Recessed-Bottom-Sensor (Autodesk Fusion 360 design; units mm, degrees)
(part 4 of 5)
work_plane "WorkPlane63" AlongDistance 20.8 ExtraOffset 0
sketch "Clear stocked carriage screw tip beyond insert" plane through (0, 20.8, 0) normal (0, 1, 0) x axis (1, 0, 0)
  circle C1 centre (60.15, -65) radius 1.7
extrude "Extrude63" cut sketch "Clear stocked carriage screw tip beyond insert" along normal blind 0.6
work_plane "WorkPlane64" AlongDistance -21.4 ExtraOffset 0
sketch "Clear stocked carriage screw tip beyond insert (1)" plane through (0, -21.4, 0) normal (0, 1, 0) x axis (1, 0, 0)
  circle C1 centre (60.15, -65) radius 1.7
extrude "Extrude64" cut sketch "Clear stocked carriage screw tip beyond insert (1)" along normal blind 0.6
work_plane "WorkPlane22" AlongDistance -2.5 ExtraOffset 0
sketch "Support-free lower ramp under left inner-race pad" plane through (0, -2.5, 0) normal (0, 1, 0) x axis (1, 0, 0)
  line L1 (8.1, -9.5) -> (7, -9.5)
  line L2 (8.1, -10.7) -> (8.1, -9.5)
  line L3 (7, -9.6) -> (8.1, -10.7)
  line L4 (7, -9.5) -> (7, -9.6)
extrude "Extrude22" cut sketch "Support-free lower ramp under left inner-race pad" along normal blind 5
work_plane "WorkPlane23" AlongDistance -2.5 ExtraOffset 0
sketch "Support-free lower ramp under right inner-race pad" plane through (0, -2.5, 0) normal (0, 1, 0) x axis (1, 0, 0)
  line L1 (17, -9.5) -> (15.9, -9.5)
  line L2 (17, -9.6) -> (17, -9.5)
  line L3 (15.9, -10.7) -> (17, -9.6)
  line L4 (15.9, -9.5) -> (15.9, -10.7)
extrude "Extrude23" cut sketch "Support-free lower ramp under right inner-race pad" along normal blind 5
ground "Pin94"
ground "Pin95"
ground "Pin100"
ground "Pin101"
ground "Pin102"
ground "Pin103"
ground "Pin104"
ground "Pin105"
ground "Pin106"
ground "Pin107"
ground "Pin108"
ground "Pin109"
ground "Pin110"
ground "Pin111"
ground "Pin112"
ground "Pin113"
ground "Pin120"
ground "Pin121"
ground "Pin122"
ground "Pin123"
work_plane "WorkPlane65" AlongDistance 36 ExtraOffset 0
sketch "Remove Oldham carriage extensions" plane through (36, 0, 0) normal (1, 0, 0) x axis (0, 0, -1)
  line L1 (-46, 34) -> (-46, -34)
  line L2 (-84, 34) -> (-46, 34)
  line L3 (-84, -34) -> (-84, 34)
  line L4 (-46, -34) -> (-84, -34)
extrude "Extrude65" cut sketch "Remove Oldham carriage extensions" along normal blind 30.3
work_plane "WorkPlane66" AlongDistance 24 ExtraOffset 0
sketch "Upper geared sensor support" plane through (24, 0, 0) normal (1, 0, 0) x axis (0, 0, -1)
  line L1 (-78, -10) -> (-78, -23)
  line L2 (-126, -10) -> (-78, -10)
  line L3 (-126, -23) -> (-126, -10)
  line L4 (-78, -23) -> (-126, -23)
extrude "Extrude66" add sketch "Upper geared sensor support" along normal blind 10
work_plane "WorkPlane67" AlongDistance 24 ExtraOffset 0
sketch "Geared mount M3 insert from inboard face" plane through (24, 0, 0) normal (1, 0, 0) x axis (0, 0, -1)
  circle C1 centre (-110.15, -16) radius 2
extrude "Extrude67" cut sketch "Geared mount M3 insert from inboard face" along normal blind 6.8
work_plane "WorkPlane68" AlongDistance 30.7 ExtraOffset 0
sketch "Geared mount screw clearance" plane through (30.7, 0, 0) normal (1, 0, 0) x axis (0, 0, -1)
  circle C1 centre (-110.15, -16) radius 1.7
extrude "Extrude68" cut sketch "Geared mount screw clearance" along normal blind 3.4
work_plane "WorkPlane69" AlongDistance 24 ExtraOffset 0
sketch "Upper geared sensor support (1)" plane through (24, 0, 0) normal (1, 0, 0) x axis (0, 0, -1)
  line L1 (-78, 23) -> (-78, 10)
  line L2 (-126, 23) -> (-78, 23)
  line L3 (-126, 10) -> (-126, 23)
  line L4 (-78, 10) -> (-126, 10)
extrude "Extrude69" add sketch "Upper geared sensor support (1)" along normal blind 10
work_plane "WorkPlane70" AlongDistance 24 ExtraOffset 0
sketch "Geared mount M3 insert from inboard face (1)" plane through (24, 0, 0) normal (1, 0, 0) x axis (0, 0, -1)
  circle C1 centre (-110.15, 16) radius 2
extrude "Extrude70" cut sketch "Geared mount M3 insert from inboard face (1)" along normal blind 6.8
work_plane "WorkPlane71" AlongDistance 30.7 ExtraOffset 0
sketch "Geared mount screw clearance (1)" plane through (30.7, 0, 0) normal (1, 0, 0) x axis (0, 0, -1)
  circle C1 centre (-110.15, 16) radius 1.7
extrude "Extrude71" cut sketch "Geared mount screw clearance (1)" along normal blind 3.4
work_plane "WorkPlane1" AlongDistance -37.35 ExtraOffset 0
sketch "Continuous 12 mm journals" plane through (-37.35, 0, 0) normal (1, 0, 0) x axis (0, 0, -1)
  circle C1 centre (-65, 0) radius 6
extrude "Extrude1" new body sketch "Continuous 12 mm journals" along normal blind 74.7 bodies "P05G Shaft lower half"
work_plane "WorkPlane2" AlongDistance -23.8 ExtraOffset 0
sketch "Structural shaft" plane through (-23.8, 0, 0) normal (1, 0, 0) x axis (0, 0, -1)
  circle C1 centre (-65, 0) radius 8
extrude "Extrude2" add sketch "Structural shaft" along normal blind 47.6
work_plane "WorkPlane3" AlongDistance -23.9 ExtraOffset 0
sketch "Rotor D flat" plane through (-23.9, 0, 0) normal (1, 0, 0) x axis (0, 0, -1)
  line L1 (-56, 9) -> (-56, 6.5)
  line L2 (-74, 9) -> (-56, 9)
  line L3 (-74, 6.5) -> (-74, 9)
  line L4 (-56, 6.5) -> (-74, 6.5)
extrude "Extrude3" cut sketch "Rotor D flat" along normal blind 47.8
work_plane "WorkPlane4" AlongDistance 37.35 ExtraOffset 0
sketch "Retain axial shoulder" plane through (37.35, 0, 0) normal (1, 0, 0) x axis (0, 0, -1)
  circle C1 centre (-65, 0) radius 10
extrude "Extrude4" add sketch "Retain axial shoulder" along normal blind 3
work_plane "WorkPlane5" AlongDistance 40.35 ExtraOffset 0
sketch "Short D drive stub" plane through (40.35, 0, 0) normal (1, 0, 0) x axis (0, 0, -1)
  circle C1 centre (-65, 0) radius 4
extrude "Extrude5" add sketch "Short D drive stub" along normal blind 8
work_plane "WorkPlane6" AlongDistance 40.35 ExtraOffset 0
sketch "Drive stub D flat" plane through (40.35, 0, 0) normal (1, 0, 0) x axis (0, 0, -1)
  line L1 (-60, 5) -> (-60, 3.2)
  line L2 (-70, 5) -> (-60, 5)
  line L3 (-70, 3.2) -> (-70, 5)
  line L4 (-60, 3.2) -> (-70, 3.2)
extrude "Extrude6" cut sketch "Drive stub D flat" along normal blind 8.15
work_plane "WorkPlane7" AlongDistance -37.45 ExtraOffset 0
sketch "End retention insert" plane through (-37.45, 0, 0) normal (1, 0, 0) x axis (0, 0, -1)
  circle C1 centre (-65, 0) radius 2
extrude "Extrude7" cut sketch "End retention insert" along normal blind 6.8
work_plane "WorkPlane8" AlongDistance -6.8 ExtraOffset 0
sketch "Joining insert" plane through (0, -6.8, 0) normal (0, 1, 0) x axis (1, 0, 0)
  circle C1 centre (-15, -65) radius 2
extrude "Extrude8" cut sketch "Joining insert" along normal blind 6.9
work_plane "WorkPlane9" AlongDistance -0.1 ExtraOffset 0
sketch "Joining screw clearance" plane through (0, -0.1, 0) normal (0, 1, 0) x axis (1, 0, 0)
  circle C1 centre (-15, -65) radius 1.7
extrude "Extrude9" cut sketch "Joining screw clearance" along normal blind 6.7
work_plane "WorkPlane10" AlongDistance 3.5 ExtraOffset 0
sketch "Recessed cap head" plane through (0, 3.5, 0) normal (0, 1, 0) x axis (1, 0, 0)
  circle C1 centre (-15, -65) radius 3.1
extrude "Extrude10" cut sketch "Recessed cap head" along normal blind 3.1
work_plane "WorkPlane11" AlongDistance -6.8 ExtraOffset 0
sketch "Joining insert (1)" plane through (0, -6.8, 0) normal (0, 1, 0) x axis (1, 0, 0)
  circle C1 centre (15, -65) radius 2
extrude "Extrude11" cut sketch "Joining insert (1)" along normal blind 6.9
work_plane "WorkPlane12" AlongDistance -0.1 ExtraOffset 0
sketch "Joining screw clearance (1)" plane through (0, -0.1, 0) normal (0, 1, 0) x axis (1, 0, 0)
  circle C1 centre (15, -65) radius 1.7
extrude "Extrude12" cut sketch "Joining screw clearance (1)" along normal blind 6.7
work_plane "WorkPlane13" AlongDistance 3.5 ExtraOffset 0
sketch "Recessed cap head (1)" plane through (0, 3.5, 0) normal (0, 1, 0) x axis (1, 0, 0)
  circle C1 centre (15, -65) radius 3.1
extrude "Extrude13" cut sketch "Recessed cap head (1)" along normal blind 3.1
work_plane "WorkPlane14" AlongDistance -6.6 ExtraOffset 0
sketch "Retain alignment key pocket" plane through (-6.6, 0, 0) normal (1, 0, 0) x axis (0, 0, -1)
  line L1 (-61, 1.6) -> (-61, -1.6)
  line L2 (-69, 1.6) -> (-61, 1.6)
  line L3 (-69, -1.6) -> (-69, 1.6)
  line L4 (-61, -1.6) -> (-69, -1.6)
extrude "Extrude14" cut sketch "Retain alignment key pocket" along normal blind 3.2
work_plane "WorkPlane15" AlongDistance 3.4 ExtraOffset 0
sketch "Retain alignment key pocket (1)" plane through (3.4, 0, 0) normal (1, 0, 0) x axis (0, 0, -1)
  line L1 (-61, 1.6) -> (-61, -1.6)
  line L2 (-69, 1.6) -> (-61, 1.6)
  line L3 (-69, -1.6) -> (-69, 1.6)
  line L4 (-61, -1.6) -> (-69, -1.6)
extrude "Extrude15" cut sketch "Retain alignment key pocket (1)" along normal blind 3.2
split "Split1" bodies "P05G Shaft upper half"
work_plane "WorkPlane1" AlongDistance 40.5 ExtraOffset 0
sketch "Involute gear polygon m1.25 pressure20" plane through (40.5, 0, 0) normal (1, 0, 0) x axis (0, 0, -1)
  line L1 (-63.7058, 28.408) -> (-63.7058, 28.408)
  line L2 (-63.7507, 28.7619) -> (-63.7058, 28.408)
  line L3 (-63.8186, 29.1167) -> (-63.7507, 28.7619)
  line L4 (-63.9051, 29.4719) -> (-63.8186, 29.1167)
  line L5 (-64.0079, 29.8273) -> (-63.9051, 29.4719)
  line L6 (-64.1255, 30.1826) -> (-64.0079, 29.8273)
  line L7 (-64.257, 30.5378) -> (-64.1255, 30.1826)
  line L8 (-64.4015, 30.8926) -> (-64.257, 30.5378)
  line L9 (-64.5586, 31.2469) -> (-64.4015, 30.8926)
  line L10 (-65.4414, 31.2469) -> (-64.5586, 31.2469)
  line L11 (-65.5985, 30.8926) -> (-65.4414, 31.2469)
  line L12 (-65.743, 30.5378) -> (-65.5985, 30.8926)
  line L13 (-65.8745, 30.1826) -> (-65.743, 30.5378)
  line L14 (-65.9921, 29.8273) -> (-65.8745, 30.1826)
  line L15 (-66.0949, 29.4719) -> (-65.9921, 29.8273)
  line L16 (-66.1814, 29.1167) -> (-66.0949, 29.4719)
  line L17 (-66.2493, 28.7619) -> (-66.1814, 29.1167)
  line L18 (-66.2942, 28.408) -> (-66.2493, 28.7619)
  line L19 (-66.2942, 28.408) -> (-66.2942, 28.408)
  line L20 (-66.5771, 28.3937) -> (-66.2942, 28.408)
  line L21 (-66.8599, 28.3766) -> (-66.5771, 28.3937)
  line L22 (-67.1425, 28.3567) -> (-66.8599, 28.3766)
  line L23 (-67.4248, 28.3339) -> (-67.1425, 28.3567)
  line L24 (-67.4248, 28.3339) -> (-67.4248, 28.3339)
  line L25 (-67.5156, 28.6789) -> (-67.4248, 28.3339)
  line L26 (-67.6292, 29.0218) -> (-67.5156, 28.6789)
  line L27 (-67.7613, 29.3626) -> (-67.6292, 29.0218)
  line L28 (-67.9096, 29.7016) -> (-67.7613, 29.3626)
  line L29 (-68.0726, 30.0386) -> (-67.9096, 29.7016)
  line L30 (-68.2493, 30.3736) -> (-68.0726, 30.0386)
  line L31 (-68.4389, 30.7065) -> (-68.2493, 30.3736)
  line L32 (-68.6409, 31.0372) -> (-68.4389, 30.7065)
  line L33 (-69.5162, 30.9219) -> (-68.6409, 31.0372)
  line L34 (-69.6257, 30.5502) -> (-69.5162, 30.9219)
  line L35 (-69.7227, 30.1796) -> (-69.6257, 30.5502)
  line L36 (-69.8066, 29.8103) -> (-69.7227, 30.1796)
  line L37 (-69.8769, 29.4426) -> (-69.8066, 29.8103)
  line L38 (-69.9324, 29.0768) -> (-69.8769, 29.4426)
  line L39 (-69.9718, 28.7134) -> (-69.9324, 29.0768)
  line L40 (-69.9928, 28.3528) -> (-69.9718, 28.7134)
  line L41 (-69.9911, 27.9961) -> (-69.9928, 28.3528)
  line L42 (-69.9911, 27.9961) -> (-69.9911, 27.9961)
  line L43 (-70.2698, 27.945) -> (-69.9911, 27.9961)
  line L44 (-70.5479, 27.8911) -> (-70.2698, 27.945)
  line L45 (-70.8254, 27.8344) -> (-70.5479, 27.8911)
  line L46 (-71.1024, 27.775) -> (-70.8254, 27.8344)
  line L47 (-71.1024, 27.775) -> (-71.1024, 27.775)
  line L48 (-71.2374, 28.1052) -> (-71.1024, 27.775)
  line L49 (-71.3948, 28.4303) -> (-71.2374, 28.1052)
  line L50 (-71.5703, 28.751) -> (-71.3948, 28.4303)
  line L51 (-71.7616, 29.0677) -> (-71.5703, 28.751)
  line L52 (-71.9672, 29.3805) -> (-71.7616, 29.0677)
  line L53 (-72.1861, 29.6896) -> (-71.9672, 29.3805)
  line L54 (-72.4175, 29.9949) -> (-72.1861, 29.6896)
  line L55 (-72.6609, 30.2964) -> (-72.4175, 29.9949)
  line L56 (-73.5136, 30.0679) -> (-72.6609, 30.2964)
  line L57 (-73.5737, 29.6851) -> (-73.5136, 30.0679)
  line L58 (-73.6215, 29.305) -> (-73.5737, 29.6851)
  line L59 (-73.6565, 28.9279) -> (-73.6215, 29.305)
  line L60 (-73.6782, 28.5541) -> (-73.6565, 28.9279)
  line L61 (-73.6854, 28.1843) -> (-73.6782, 28.5541)
  line L62 (-73.6771, 27.8188) -> (-73.6854, 28.1843)
  line L63 (-73.6509, 27.4586) -> (-73.6771, 27.8188)
  line L64 (-73.6027, 27.1051) -> (-73.6509, 27.4586)
  line L65 (-73.6027, 27.1051) -> (-73.6027, 27.1051)
  line L66 (-73.8722, 27.018) -> (-73.6027, 27.1051)
  line L67 (-74.1409, 26.9283) -> (-73.8722, 27.018)
  line L68 (-74.4087, 26.8359) -> (-74.1409, 26.9283)
  line L69 (-74.6756, 26.7409) -> (-74.4087, 26.8359)
  line L70 (-74.6756, 26.7409) -> (-74.6756, 26.7409)
  line L71 (-74.8525, 27.0507) -> (-74.6756, 26.7409)
  line L72 (-75.051, 27.3524) -> (-74.8525, 27.0507)
  line L73 (-75.2669, 27.6474) -> (-75.051, 27.3524)
  line L74 (-75.4978, 27.9365) -> (-75.2669, 27.6474)
  line L75 (-75.7425, 28.2198) -> (-75.4978, 27.9365)
  line L76 (-75.9999, 28.4976) -> (-75.7425, 28.2198)
  line L77 (-76.2692, 28.7701) -> (-75.9999, 28.4976)
  line L78 (-76.5499, 29.0373) -> (-76.2692, 28.7701)
  line L79 (-77.3655, 28.6994) -> (-76.5499, 29.0373)
  line L80 (-77.375, 28.3121) -> (-77.3655, 28.6994)
  line L81 (-77.3728, 27.9289) -> (-77.375, 28.3121)
  line L82 (-77.3583, 27.5505) -> (-77.3728, 27.9289)
  line L83 (-77.331, 27.1771) -> (-77.3583, 27.5505)
  line L84 (-77.2899, 26.8095) -> (-77.331, 27.1771)
  line L85 (-77.2339, 26.4482) -> (-77.2899, 26.8095)
  line L86 (-77.1609, 26.0945) -> (-77.2339, 26.4482)
  line L87 (-77.067, 25.7503) -> (-77.1609, 26.0945)
  line L88 (-77.067, 25.7503) -> (-77.067, 25.7503)
  line L89 (-77.3229, 25.6288) -> (-77.067, 25.7503)
  line L90 (-77.5776, 25.5048) -> (-77.3229, 25.6288)
  line L91 (-77.831, 25.3783) -> (-77.5776, 25.5048)
  line L92 (-78.0832, 25.2492) -> (-77.831, 25.3783)
  line L93 (-78.0832, 25.2492) -> (-78.0832, 25.2492)
  line L94 (-78.299, 25.5332) -> (-78.0832, 25.2492)
  line L95 (-78.5352, 25.8065) -> (-78.299, 25.5332)
  line L96 (-78.7877, 26.0708) -> (-78.5352, 25.8065)
  line L97 (-79.0544, 26.3272) -> (-78.7877, 26.0708)
  line L98 (-79.334, 26.5762) -> (-79.0544, 26.3272)
  line L99 (-79.6254, 26.8181) -> (-79.334, 26.5762)
  line L100 (-79.928, 27.0531) -> (-79.6254, 26.8181)
  line L101 (-80.2412, 27.2813) -> (-79.928, 27.0531)
  line L102 (-81.0057, 26.8399) -> (-80.2412, 27.2813)
  line L103 (-80.9646, 26.4546) -> (-81.0057, 26.8399)
  line L104 (-80.9124, 26.075) -> (-80.9646, 26.4546)
  line L105 (-80.8487, 25.7017) -> (-80.9124, 26.075)
  line L106 (-80.7728, 25.3351) -> (-80.8487, 25.7017)
  line L107 (-80.6841, 24.9759) -> (-80.7728, 25.3351)
  line L108 (-80.5814, 24.6251) -> (-80.6841, 24.9759)
  line L109 (-80.4629, 24.2839) -> (-80.5814, 24.6251)
  line L110 (-80.3249, 23.955) -> (-80.4629, 24.2839)
  line L111 (-80.3249, 23.955) -> (-80.3249, 23.955)
  line L112 (-80.5627, 23.8011) -> (-80.3249, 23.955)
  line L113 (-80.799, 23.6449) -> (-80.5627, 23.8011)
  line L114 (-81.0338, 23.4864) -> (-80.799, 23.6449)
  line L115 (-81.2669, 23.3255) -> (-81.0338, 23.4864)
  line L116 (-81.2669, 23.3255) -> (-81.2669, 23.3255)
  line L117 (-81.518, 23.5789) -> (-81.2669, 23.3255)
  line L118 (-81.7879, 23.819) -> (-81.518, 23.5789)
  line L119 (-82.0727, 24.0481) -> (-81.7879, 23.819)
  line L120 (-82.3706, 24.2675) -> (-82.0727, 24.0481)
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extrude "Extrude1" new body sketch "Involute gear polygon m1.25 pressure20" along normal blind 8 bodies "G01R 48T gear with upper clamp"
work_plane "WorkPlane2" AlongDistance 40.4 ExtraOffset 0
sketch "Shaft bore" plane through (40.4, 0, 0) normal (1, 0, 0) x axis (0, 0, -1)
  circle C1 centre (-65, 0) radius 4.1
extrude "Extrude2" cut sketch "Shaft bore" along normal blind 8.2
work_plane "WorkPlane3" AlongDistance 40.5 ExtraOffset 0
sketch "D key flat" plane through (40.5, 0, 0) normal (1, 0, 0) x axis (0, 0, -1)
  line L1 (-62, 4.3) -> (-62, 3.35)
  line L2 (-68, 4.3) -> (-62, 4.3)
  line L3 (-68, 3.35) -> (-68, 4.3)
  line L4 (-62, 3.35) -> (-68, 3.35)
extrude "Extrude3" add sketch "D key flat" along normal blind 8
work_plane "WorkPlane4" AlongDistance 40.4 ExtraOffset 0
sketch "Clamp slit outside operating mesh sector" plane through (40.4, 0, 0) normal (1, 0, 0) x axis (0, 0, -1)
  line L1 (-32, 0.2) -> (-32, -0.2)
  line L2 (-65, 0.2) -> (-32, 0.2)
  line L3 (-65, -0.2) -> (-65, 0.2)
  line L4 (-32, -0.2) -> (-65, -0.2)
work_plane "WorkPlane5" AlongDistance -8 ExtraOffset 0
sketch "Clamp heat-set insert pocket" plane through (0, -8, 0) normal (0, 1, 0) x axis (1, 0, 0)
  circle C1 centre (44.5, -57) radius 2
work_plane "WorkPlane6" AlongDistance -1.3 ExtraOffset 0
sketch "Clamp through screw" plane through (0, -1.3, 0) normal (0, 1, 0) x axis (1, 0, 0)
  circle C1 centre (44.5, -57) radius 1.7
work_plane "WorkPlane7" AlongDistance 5 ExtraOffset 0
sketch "Recessed clamp screw head and tool path" plane through (0, 5, 0) normal (0, 1, 0) x axis (1, 0, 0)
  circle C1 centre (44.5, -57) radius 3.1
work_plane "WorkPlane1" AlongDistance 40.5 ExtraOffset 0
sketch "Involute gear polygon m1.25 pressure20" plane through (40.5, 0, 0) normal (1, 0, 0) x axis (0, 0, -1)
  line L1 (-110.8997, 14.0754) -> (-110.8647, 13.4185)
  line L2 (-110.9494, 14.3425) -> (-110.8997, 14.0754)
  line L3 (-111.0295, 14.6076) -> (-110.9494, 14.3425)
  line L4 (-111.1304, 14.8711) -> (-111.0295, 14.6076)
  line L5 (-111.2488, 15.1329) -> (-111.1304, 14.8711)
  line L6 (-111.383, 15.3927) -> (-111.2488, 15.1329)
  line L7 (-111.5317, 15.6505) -> (-111.383, 15.3927)
  line L8 (-111.6943, 15.9059) -> (-111.5317, 15.6505)
  line L9 (-111.87, 16.1587) -> (-111.6943, 15.9059)
  line L10 (-112.6708, 16.0533) -> (-111.87, 16.1587)
  line L11 (-112.7751, 15.7636) -> (-112.6708, 16.0533)
  line L12 (-112.866, 15.4748) -> (-112.7751, 15.7636)
  line L13 (-112.943, 15.1873) -> (-112.866, 15.4748)
  line L14 (-113.0053, 14.9016) -> (-112.943, 15.1873)
  line L15 (-113.0519, 14.6181) -> (-113.0053, 14.9016)
  line L16 (-113.0812, 14.3375) -> (-113.0519, 14.6181)
  line L17 (-113.0899, 14.0607) -> (-113.0812, 14.3375)
  line L18 (-113.0688, 13.7899) -> (-113.0899, 14.0607)
  line L19 (-112.9326, 13.1462) -> (-113.0688, 13.7899)
  line L20 (-113.2814, 13.0676) -> (-112.9326, 13.1462)
  line L21 (-113.6279, 12.9796) -> (-113.2814, 13.0676)
  line L22 (-113.9719, 12.8825) -> (-113.6279, 12.9796)
  line L23 (-114.3133, 12.7763) -> (-113.9719, 12.8825)
  line L24 (-114.5171, 13.4018) -> (-114.3133, 12.7763)
  line L25 (-114.6343, 13.6468) -> (-114.5171, 13.4018)
  line L26 (-114.7803, 13.8822) -> (-114.6343, 13.6468)
  line L27 (-114.9459, 14.1106) -> (-114.7803, 13.8822)
  line L28 (-115.128, 14.3328) -> (-114.9459, 14.1106)
  line L29 (-115.3249, 14.5491) -> (-115.128, 14.3328)
  line L30 (-115.5353, 14.7596) -> (-115.3249, 14.5491)
  line L31 (-115.7584, 14.9642) -> (-115.5353, 14.7596)
  line L32 (-115.9936, 15.1629) -> (-115.7584, 14.9642)
  line L33 (-116.7398, 14.8539) -> (-115.9936, 15.1629)
  line L34 (-116.7656, 14.547) -> (-116.7398, 14.8539)
  line L35 (-116.7786, 14.2446) -> (-116.7656, 14.547)
  line L36 (-116.7786, 13.947) -> (-116.7786, 14.2446)
  line L37 (-116.7649, 13.6548) -> (-116.7786, 13.947)
  line L38 (-116.7365, 13.3689) -> (-116.7649, 13.6548)
  line L39 (-116.6921, 13.0903) -> (-116.7365, 13.3689)
  line L40 (-116.6289, 12.8206) -> (-116.6921, 13.0903)
  line L41 (-116.5385, 12.5645) -> (-116.6289, 12.8206)
  line L42 (-116.2403, 11.9781) -> (-116.5385, 12.5645)
  line L43 (-116.5568, 11.8118) -> (-116.2403, 11.9781)
  line L44 (-116.8688, 11.6372) -> (-116.5568, 11.8118)
  line L45 (-117.176, 11.4544) -> (-116.8688, 11.6372)
  line L46 (-117.4782, 11.2634) -> (-117.176, 11.4544)
  line L47 (-117.837, 11.8148) -> (-117.4782, 11.2634)
  line L48 (-118.0136, 12.0212) -> (-117.837, 11.8148)
  line L49 (-118.2155, 12.2108) -> (-118.0136, 12.0212)
  line L50 (-118.4346, 12.3885) -> (-118.2155, 12.2108)
  line L51 (-118.668, 12.556) -> (-118.4346, 12.3885)
  line L52 (-118.9141, 12.714) -> (-118.668, 12.556)
  line L53 (-119.1718, 12.8628) -> (-118.9141, 12.714)
  line L54 (-119.4403, 13.0028) -> (-119.1718, 12.8628)
  line L55 (-119.7189, 13.1339) -> (-119.4403, 13.0028)
  line L56 (-120.3597, 12.6422) -> (-119.7189, 13.1339)
  line L57 (-120.3052, 12.3391) -> (-120.3597, 12.6422)
  line L58 (-120.2395, 12.0436) -> (-120.3052, 12.3391)
  line L59 (-120.1625, 11.7561) -> (-120.2395, 12.0436)
  line L60 (-120.0736, 11.4775) -> (-120.1625, 11.7561)
  line L61 (-119.9722, 11.2087) -> (-120.0736, 11.4775)
  line L62 (-119.8572, 10.951) -> (-119.9722, 11.2087)
  line L63 (-119.7264, 10.7069) -> (-119.8572, 10.951)
  line L64 (-119.5727, 10.4829) -> (-119.7264, 10.7069)
  line L65 (-119.1329, 9.9937) -> (-119.5727, 10.4829)
  line L66 (-119.3956, 9.7512) -> (-119.1329, 9.9937)
  line L67 (-119.6517, 9.5017) -> (-119.3956, 9.7512)
  line L68 (-119.9012, 9.2456) -> (-119.6517, 9.5017)
  line L69 (-120.1437, 8.9829) -> (-119.9012, 9.2456)
  line L70 (-120.6329, 9.4227) -> (-120.1437, 8.9829)
  line L71 (-120.8569, 9.5764) -> (-120.6329, 9.4227)
  line L72 (-121.101, 9.7072) -> (-120.8569, 9.5764)
  line L73 (-121.3587, 9.8222) -> (-121.101, 9.7072)
  line L74 (-121.6275, 9.9236) -> (-121.3587, 9.8222)
  line L75 (-121.9061, 10.0125) -> (-121.6275, 9.9236)
  line L76 (-122.1936, 10.0895) -> (-121.9061, 10.0125)
  line L77 (-122.4891, 10.1552) -> (-122.1936, 10.0895)
  line L78 (-122.7922, 10.2097) -> (-122.4891, 10.1552)
  line L79 (-123.2839, 9.5689) -> (-122.7922, 10.2097)
  line L80 (-123.1528, 9.2903) -> (-123.2839, 9.5689)
  line L81 (-123.0128, 9.0218) -> (-123.1528, 9.2903)
  line L82 (-122.864, 8.7641) -> (-123.0128, 9.0218)
  line L83 (-122.706, 8.518) -> (-122.864, 8.7641)
  line L84 (-122.5385, 8.2846) -> (-122.706, 8.518)
  line L85 (-122.3608, 8.0655) -> (-122.5385, 8.2846)
  line L86 (-122.1712, 7.8636) -> (-122.3608, 8.0655)
  line L87 (-121.9648, 7.687) -> (-122.1712, 7.8636)
  line L88 (-121.4134, 7.3282) -> (-121.9648, 7.687)
  line L89 (-121.6044, 7.026) -> (-121.4134, 7.3282)
  line L90 (-121.7872, 6.7187) -> (-121.6044, 7.026)
  line L91 (-121.9618, 6.4068) -> (-121.7872, 6.7187)
  line L92 (-122.1281, 6.0903) -> (-121.9618, 6.4068)
  line L93 (-122.7145, 6.3885) -> (-122.1281, 6.0903)
  line L94 (-122.9706, 6.4789) -> (-122.7145, 6.3885)
  line L95 (-123.2403, 6.5421) -> (-122.9706, 6.4789)
  line L96 (-123.5189, 6.5865) -> (-123.2403, 6.5421)
  line L97 (-123.8048, 6.6149) -> (-123.5189, 6.5865)
  line L98 (-124.097, 6.6286) -> (-123.8048, 6.6149)
  line L99 (-124.3946, 6.6286) -> (-124.097, 6.6286)
  line L100 (-124.697, 6.6156) -> (-124.3946, 6.6286)
  line L101 (-125.0039, 6.5898) -> (-124.697, 6.6156)
  line L102 (-125.3129, 5.8436) -> (-125.0039, 6.5898)
  line L103 (-125.1142, 5.6084) -> (-125.3129, 5.8436)
  line L104 (-124.9096, 5.3853) -> (-125.1142, 5.6084)
  line L105 (-124.6991, 5.1749) -> (-124.9096, 5.3853)
  line L106 (-124.4828, 4.978) -> (-124.6991, 5.1749)
  line L107 (-124.2606, 4.7959) -> (-124.4828, 4.978)
  line L108 (-124.0322, 4.6303) -> (-124.2606, 4.7959)
  line L109 (-123.7968, 4.4843) -> (-124.0322, 4.6303)
  line L110 (-123.5518, 4.3671) -> (-123.7968, 4.4843)
  line L111 (-122.9263, 4.1633) -> (-123.5518, 4.3671)
  line L112 (-123.0325, 3.8219) -> (-122.9263, 4.1633)
  line L113 (-123.1296, 3.4779) -> (-123.0325, 3.8219)
  line L114 (-123.2176, 3.1314) -> (-123.1296, 3.4779)
  line L115 (-123.2962, 2.7826) -> (-123.2176, 3.1314)
  line L116 (-123.9399, 2.9188) -> (-123.2962, 2.7826)
  line L117 (-124.2107, 2.9399) -> (-123.9399, 2.9188)
  line L118 (-124.4875, 2.9312) -> (-124.2107, 2.9399)
  line L119 (-124.7681, 2.9019) -> (-124.4875, 2.9312)
  line L120 (-125.0516, 2.8553) -> (-124.7681, 2.9019)
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extrude "Extrude1" new body sketch "Involute gear polygon m1.25 pressure20" along normal blind 8 bodies "G02 24T sensor pinion"
work_plane "WorkPlane2" AlongDistance 40.4 ExtraOffset 0
sketch "Shaft bore" plane through (40.4, 0, 0) normal (1, 0, 0) x axis (0, 0, -1)
  circle C1 centre (-110.15, 0) radius 3.1
extrude "Extrude2" cut sketch "Shaft bore" along normal blind 8.2
work_plane "WorkPlane3" AlongDistance 40.4 ExtraOffset 0
sketch "Sensor bushing end relief" plane through (40.4, 0, 0) normal (1, 0, 0) x axis (0, 0, -1)
  circle C1 centre (-110.15, 0) radius 3.6
extrude "Extrude3" cut sketch "Sensor bushing end relief" along normal blind 0.9
work_plane "WorkPlane4" AlongDistance 40.4 ExtraOffset 0
sketch "Clamp slit outside operating mesh sector" plane through (40.4, 0, 0) normal (1, 0, 0) x axis (0, 0, -1)
  line L1 (-110.15, 0.2) -> (-110.15, -0.2)
  line L2 (-127, 0.2) -> (-110.15, 0.2)
  line L3 (-127, -0.2) -> (-127, 0.2)
  line L4 (-110.15, -0.2) -> (-127, -0.2)
extrude "Extrude4" cut sketch "Clamp slit outside operating mesh sector" along normal blind 8.2
work_plane "WorkPlane5" AlongDistance -8 ExtraOffset 0
sketch "Clamp heat-set insert pocket" plane through (0, -8, 0) normal (0, 1, 0) x axis (1, 0, 0)
  circle C1 centre (44.5, -118.15) radius 2
work_plane "WorkPlane6" AlongDistance -1.3 ExtraOffset 0
sketch "Clamp through screw" plane through (0, -1.3, 0) normal (0, 1, 0) x axis (1, 0, 0)
  circle C1 centre (44.5, -118.15) radius 1.7
work_plane "WorkPlane7" AlongDistance 5 ExtraOffset 0
sketch "Recessed clamp screw head and tool path" plane through (0, 5, 0) normal (0, 1, 0) x axis (1, 0, 0)
  circle C1 centre (44.5, -118.15) radius 3.1
work_plane "WorkPlane1" AlongDistance 20 ExtraOffset 0
sketch "Provisional sensor body" plane through (20, 0, 0) normal (1, 0, 0) x axis (0, 0, -1)
  line L1 (-105.4, 4.75) -> (-105.4, -4.75)
  line L2 (-114.9, 4.75) -> (-105.4, 4.75)
  line L3 (-114.9, -4.75) -> (-114.9, 4.75)
  line L4 (-105.4, -4.75) -> (-114.9, -4.75)
extrude "Extrude1" new body sketch "Provisional sensor body" along normal blind 14 bodies "REFERENCE Geared RK097 provisional envelope"
work_plane "WorkPlane2" AlongDistance 34 ExtraOffset 0
sketch "Provisional bushing" plane through (34, 0, 0) normal (1, 0, 0) x axis (0, 0, -1)
  circle C1 centre (-110.15, 0) radius 3.5
extrude "Extrude2" add sketch "Provisional bushing" along normal blind 7
work_plane "WorkPlane3" AlongDistance 41 ExtraOffset 0
sketch "Provisional 12 mm exposed shaft" plane through (41, 0, 0) normal (1, 0, 0) x axis (0, 0, -1)
  circle C1 centre (-110.15, 0) radius 3
extrude "Extrude3" add sketch "Provisional 12 mm exposed shaft" along normal blind 12
work_plane "WorkPlane1" AlongDistance 37 ExtraOffset 0
sketch "Geared RK097 supplied washer ASSUMED" plane through (37, 0, 0) normal (1, 0, 0) x axis (0, 0, -1)
  circle C1 centre (-110.15, 0) radius 6
extrude "Extrude1" new body sketch "Geared RK097 supplied washer ASSUMED" along normal blind 0.5 bodies "HARDWARE Geared RK097 supplied washer ASSUMED"
work_plane "WorkPlane2" AlongDistance 36.9 ExtraOffset 0
sketch "Washer clearance" plane through (36.9, 0, 0) normal (1, 0, 0) x axis (0, 0, -1)
  circle C1 centre (-110.15, 0) radius 3.6
extrude "Extrude2" cut sketch "Washer clearance" along normal blind 0.7
work_plane "WorkPlane1" AlongDistance 37.5 ExtraOffset 0
sketch "Geared RK097 supplied nut ASSUMED" plane through (37.5, 0, 0) normal (1, 0, 0) x axis (0, 0, -1)
  line L1 (-115.65, 3.1754) -> (-110.15, 6.3509)
  line L2 (-115.65, -3.1754) -> (-115.65, 3.1754)
  line L3 (-110.15, -6.3509) -> (-115.65, -3.1754)
  line L4 (-104.65, -3.1754) -> (-110.15, -6.3509)
  line L5 (-104.65, 3.1754) -> (-104.65, -3.1754)
  line L6 (-110.15, 6.3509) -> (-104.65, 3.1754)
extrude "Extrude1" new body sketch "Geared RK097 supplied nut ASSUMED" along normal blind 2 bodies "HARDWARE Geared RK097 supplied nut ASSUMED"
work_plane "WorkPlane2" AlongDistance 37.4 ExtraOffset 0
sketch "Thread envelope" plane through (37.4, 0, 0) normal (1, 0, 0) x axis (0, 0, -1)
  circle C1 centre (-110.15, 0) radius 3.5
extrude "Extrude2" cut sketch "Thread envelope" along normal blind 2.2
work_plane "WorkPlane8" AlongDistance -7 ExtraOffset 0
sketch "Revised clamp insert pocket" plane through (0, -7, 0) normal (0, 1, 0) x axis (1, 0, 0)
  circle C1 centre (44.5, -117.65) radius 2
extrude "Extrude8" cut sketch "Revised clamp insert pocket" along normal blind 6.8
work_plane "WorkPlane9" AlongDistance -0.3 ExtraOffset 0
sketch "Revised clamp screw clearance" plane through (0, -0.3, 0) normal (0, 1, 0) x axis (1, 0, 0)
  circle C1 centre (44.5, -117.65) radius 1.7
extrude "Extrude9" cut sketch "Revised clamp screw clearance" along normal blind 5.4
work_plane "WorkPlane10" AlongDistance 5 ExtraOffset 0
sketch "Revised recessed clamp head" plane through (0, 5, 0) normal (0, 1, 0) x axis (1, 0, 0)
  circle C1 centre (44.5, -117.65) radius 3.1
extrude "Extrude10" cut sketch "Revised recessed clamp head" along normal blind 30
work_plane "WorkPlane1" AlongDistance -7 ExtraOffset 0
sketch "G02 24T sensor pinion clamp M3x12" plane through (0, -7, 0) normal (0, 1, 0) x axis (1, 0, 0)
  circle C1 centre (44.5, -117.65) radius 1.5
extrude "Extrude1" new body sketch "G02 24T sensor pinion clamp M3x12" along normal blind 12 bodies "HARDWARE G02 24T sensor pinion clamp M3x12"
work_plane "WorkPlane2" AlongDistance 5 ExtraOffset 0
sketch "Button head" plane through (0, 5, 0) normal (0, 1, 0) x axis (1, 0, 0)
  circle C1 centre (44.5, -117.65) radius 2.75
extrude "Extrude2" add sketch "Button head" along normal blind 3
work_plane "WorkPlane11" AlongDistance 40.4 ExtraOffset 0
sketch "Open support-free clamp tool channel" plane through (40.4, 0, 0) normal (1, 0, 0) x axis (0, 0, -1)
  line L1 (-114.55, 18) -> (-114.55, 5)
  line L2 (-120.75, 18) -> (-114.55, 18)
  line L3 (-120.75, 5) -> (-120.75, 18)
  line L4 (-114.55, 5) -> (-120.75, 5)
extrude "Extrude11" cut sketch "Open support-free clamp tool channel" along normal blind 8.2
position "Position1"
work_plane "WorkPlane68" AlongDistance -36.1 ExtraOffset 0
sketch "Remove above-rail flange" plane through (-36.1, 0, 0) normal (1, 0, 0) x axis (0, 0, -1)
  line L1 (-50, -75) -> (-50, -96)
  line L2 (-90, -75) -> (-50, -75)
  line L3 (-90, -96) -> (-90, -75)
  line L4 (-50, -96) -> (-90, -96)
extrude "Extrude68" cut sketch "Remove above-rail flange" along normal blind 12.2
work_plane "WorkPlane69" AlongDistance -36 ExtraOffset 0
sketch "Underside rail suspension arm" plane through (-36, 0, 0) normal (1, 0, 0) x axis (0, 0, -1)
  line L1 (-33, -75) -> (-33, -55)
  line L2 (-73, -75) -> (-33, -75)
  line L3 (-73, -95) -> (-73, -75)
  line L4 (-82, -95) -> (-73, -95)
  line L5 (-82, -65) -> (-82, -95)
  line L6 (-57, -55) -> (-82, -65)
  line L7 (-33, -55) -> (-57, -55)
work_plane "WorkPlane70" AlongDistance 72.9 ExtraOffset 0
sketch "Underside M5 clearance" plane through (0, 0, 72.9) normal (0, 0, 1) x axis (1, 0, 0)
  circle C1 centre (-30, -85) radius 2.7
work_plane "WorkPlane71" AlongDistance -36.1 ExtraOffset 0
sketch "Remove above-rail flange (1)" plane through (-36.1, 0, 0) normal (1, 0, 0) x axis (0, 0, -1)
  line L1 (-50, 96) -> (-50, 75)
  line L2 (-90, 96) -> (-50, 96)
  line L3 (-90, 75) -> (-90, 96)
  line L4 (-50, 75) -> (-90, 75)
extrude "Extrude71" cut sketch "Remove above-rail flange (1)" along normal blind 12.2
work_plane "WorkPlane72" AlongDistance -36 ExtraOffset 0
sketch "Underside rail suspension arm (1)" plane through (-36, 0, 0) normal (1, 0, 0) x axis (0, 0, -1)
  line L1 (-33, 75) -> (-33, 55)
  line L2 (-73, 75) -> (-33, 75)
  line L3 (-73, 95) -> (-73, 75)
  line L4 (-82, 95) -> (-73, 95)
  line L5 (-82, 65) -> (-82, 95)
  line L6 (-57, 55) -> (-82, 65)
  line L7 (-33, 55) -> (-57, 55)
work_plane "WorkPlane73" AlongDistance 72.9 ExtraOffset 0
sketch "Underside M5 clearance (1)" plane through (0, 0, 72.9) normal (0, 0, 1) x axis (1, 0, 0)
  circle C1 centre (-30, 85) radius 2.7
work_plane "WorkPlane72" AlongDistance 23.9 ExtraOffset 0
sketch "Remove above-rail flange" plane through (23.9, 0, 0) normal (1, 0, 0) x axis (0, 0, -1)
  line L1 (-50, -75) -> (-50, -96)
  line L2 (-90, -75) -> (-50, -75)
  line L3 (-90, -96) -> (-90, -75)
  line L4 (-50, -96) -> (-90, -96)
extrude "Extrude72" cut sketch "Remove above-rail flange" along normal blind 12.2
work_plane "WorkPlane73" AlongDistance 24 ExtraOffset 0
sketch "Underside rail suspension arm" plane through (24, 0, 0) normal (1, 0, 0) x axis (0, 0, -1)
  line L1 (-33, -75) -> (-33, -55)
  line L2 (-73, -75) -> (-33, -75)
  line L3 (-73, -95) -> (-73, -75)
  line L4 (-82, -95) -> (-73, -95)
  line L5 (-82, -65) -> (-82, -95)
  line L6 (-57, -55) -> (-82, -65)
  line L7 (-33, -55) -> (-57, -55)
work_plane "WorkPlane74" AlongDistance 72.9 ExtraOffset 0
sketch "Underside M5 clearance" plane through (0, 0, 72.9) normal (0, 0, 1) x axis (1, 0, 0)
  circle C1 centre (30, -85) radius 2.7
work_plane "WorkPlane75" AlongDistance 23.9 ExtraOffset 0
sketch "Remove above-rail flange (1)" plane through (23.9, 0, 0) normal (1, 0, 0) x axis (0, 0, -1)
  line L1 (-50, 96) -> (-50, 75)
  line L2 (-90, 96) -> (-50, 96)
  line L3 (-90, 75) -> (-90, 96)
  line L4 (-50, 75) -> (-90, 75)
extrude "Extrude75" cut sketch "Remove above-rail flange (1)" along normal blind 12.2
work_plane "WorkPlane76" AlongDistance 24 ExtraOffset 0
sketch "Underside rail suspension arm (1)" plane through (24, 0, 0) normal (1, 0, 0) x axis (0, 0, -1)
  line L1 (-33, 75) -> (-33, 55)
  line L2 (-73, 75) -> (-33, 75)
  line L3 (-73, 95) -> (-73, 75)
  line L4 (-82, 95) -> (-73, 95)
  line L5 (-82, 65) -> (-82, 95)
  line L6 (-57, 55) -> (-82, 65)
  line L7 (-33, 55) -> (-57, 55)
work_plane "WorkPlane77" AlongDistance 72.9 ExtraOffset 0
sketch "Underside M5 clearance (1)" plane through (0, 0, 72.9) normal (0, 0, 1) x axis (1, 0, 0)
  circle C1 centre (30, 85) radius 2.7
work_plane "WorkPlane78" AlongDistance 23.9 ExtraOffset 0
sketch "Remove upper sensor towers" plane through (23.9, 0, 0) normal (1, 0, 0) x axis (0, 0, -1)
  line L1 (-86.01, 24) -> (-86.01, -24)
  line L2 (-127, 24) -> (-86.01, 24)
  line L3 (-127, -24) -> (-127, 24)
  line L4 (-86.01, -24) -> (-127, -24)
extrude "Extrude78" cut sketch "Remove upper sensor towers" along normal blind 10.2
work_plane "WorkPlane79" AlongDistance 24 ExtraOffset 0
sketch "Lower sensor support" plane through (24, 0, 0) normal (1, 0, 0) x axis (0, 0, -1)
  line L1 (-4, -10) -> (-4, -23)
  line L2 (-35, -10) -> (-4, -10)
  line L3 (-35, -23) -> (-35, -10)
  line L4 (-4, -23) -> (-35, -23)
work_plane "WorkPlane80" AlongDistance 24 ExtraOffset 0
sketch "Lower sensor M3 insert" plane through (24, 0, 0) normal (1, 0, 0) x axis (0, 0, -1)
  circle C1 centre (-19.85, -16) radius 2
work_plane "WorkPlane81" AlongDistance 30.7 ExtraOffset 0
sketch "Lower sensor screw clearance" plane through (30.7, 0, 0) normal (1, 0, 0) x axis (0, 0, -1)
  circle C1 centre (-19.85, -16) radius 1.7
work_plane "WorkPlane82" AlongDistance 24 ExtraOffset 0
sketch "Lower sensor support (1)" plane through (24, 0, 0) normal (1, 0, 0) x axis (0, 0, -1)
  line L1 (-4, 23) -> (-4, 10)
  line L2 (-35, 23) -> (-4, 23)
  line L3 (-35, 10) -> (-35, 23)
  line L4 (-4, 10) -> (-35, 10)
work_plane "WorkPlane83" AlongDistance 24 ExtraOffset 0
sketch "Lower sensor M3 insert (1)" plane through (24, 0, 0) normal (1, 0, 0) x axis (0, 0, -1)
  circle C1 centre (-19.85, 16) radius 2
work_plane "WorkPlane84" AlongDistance 30.7 ExtraOffset 0
sketch "Lower sensor screw clearance (1)" plane through (30.7, 0, 0) normal (1, 0, 0) x axis (0, 0, -1)
  circle C1 centre (-19.85, 16) radius 1.7
work_plane "WorkPlane85" AlongDistance 23.9 ExtraOffset 0
sketch "Potentiometer body and lead clearance" plane through (23.9, 0, 0) normal (1, 0, 0) x axis (0, 0, -1)
  line L1 (-8.5, 8) -> (-8.5, -8)
  line L2 (-31.2, 8) -> (-8.5, 8)
  line L3 (-31.2, -8) -> (-31.2, 8)
  line L4 (-8.5, -8) -> (-31.2, -8)
work_plane "WorkPlane8" AlongDistance 40.4 ExtraOffset 0
sketch "Upper clamp split clear of lower mesh" plane through (40.4, 0, 0) normal (1, 0, 0) x axis (0, 0, -1)
  line L1 (-65, 0.2) -> (-65, -0.2)
  line L2 (-98, 0.2) -> (-65, 0.2)
  line L3 (-98, -0.2) -> (-98, 0.2)
  line L4 (-65, -0.2) -> (-98, -0.2)
extrude "Extrude8" cut sketch "Upper clamp split clear of lower mesh" along normal blind 8.2
work_plane "WorkPlane9" AlongDistance -8 ExtraOffset 0
sketch "Upper clamp insert" plane through (0, -8, 0) normal (0, 1, 0) x axis (1, 0, 0)
  circle C1 centre (44.5, -73) radius 2
extrude "Extrude9" cut sketch "Upper clamp insert" along normal blind 6.8
work_plane "WorkPlane10" AlongDistance -1.3 ExtraOffset 0
sketch "Upper clamp screw clearance" plane through (0, -1.3, 0) normal (0, 1, 0) x axis (1, 0, 0)
  circle C1 centre (44.5, -73) radius 1.7
extrude "Extrude10" cut sketch "Upper clamp screw clearance" along normal blind 6.4
work_plane "WorkPlane11" AlongDistance 5 ExtraOffset 0
sketch "Upper clamp head recess" plane through (0, 5, 0) normal (0, 1, 0) x axis (1, 0, 0)
  circle C1 centre (44.5, -73) radius 3.1
extrude "Extrude11" cut sketch "Upper clamp head recess" along normal blind 30
work_plane "WorkPlane1" AlongDistance -7 ExtraOffset 0
sketch "G01 upper clamp M3x12" plane through (0, -7, 0) normal (0, 1, 0) x axis (1, 0, 0)
  circle C1 centre (44.5, -73) radius 1.5
extrude "Extrude1" new body sketch "G01 upper clamp M3x12" along normal blind 12 bodies "HARDWARE G01 upper clamp M3x12"
work_plane "WorkPlane2" AlongDistance 5 ExtraOffset 0
sketch "Button head" plane through (0, 5, 0) normal (0, 1, 0) x axis (1, 0, 0)
  circle C1 centre (44.5, -73) radius 2.75
extrude "Extrude2" add sketch "Button head" along normal blind 3
ground "Unpin124"
ground "Unpin125"
ground "Unpin126"
ground "Unpin127"
ground "Unpin128"
ground "Unpin129"
ground "Unpin130"
ground "Unpin131"
ground "Unpin132"
ground "Unpin133"
ground "Unpin134"
ground "Unpin135"
ground "Unpin136"
ground "Unpin137"
ground "Unpin138"
ground "Unpin139"
ground "Unpin140"
ground "Unpin141"
ground "Unpin142"
ground "Unpin143"
ground "Unpin144"
ground "Unpin145"
ground "Unpin146"
ground "Unpin147"
ground "Unpin148"
ground "Unpin149"
ground "Unpin150"
ground "Unpin151"
ground "Unpin152"
position "Position2"
work_plane "WorkPlane86" AlongDistance 24 ExtraOffset 0
sketch "Outer lower sensor support clear of cam" plane through (24, 0, 0) normal (1, 0, 0) x axis (0, 0, -1)
  line L1 (-4, -49) -> (-4, -62)
  line L2 (-35, -49) -> (-4, -49)
  line L3 (-35, -62) -> (-35, -49)
  line L4 (-4, -62) -> (-35, -62)
extrude "Extrude86" add sketch "Outer lower sensor support clear of cam" along normal blind 10
work_plane "WorkPlane87" AlongDistance 24 ExtraOffset 0
sketch "Outer lower M3 insert" plane through (24, 0, 0) normal (1, 0, 0) x axis (0, 0, -1)
  circle C1 centre (-19.85, -55) radius 2
extrude "Extrude87" cut sketch "Outer lower M3 insert" along normal blind 6.8
work_plane "WorkPlane88" AlongDistance 30.7 ExtraOffset 0
sketch "Outer lower screw clearance" plane through (30.7, 0, 0) normal (1, 0, 0) x axis (0, 0, -1)
  circle C1 centre (-19.85, -55) radius 1.7
extrude "Extrude88" cut sketch "Outer lower screw clearance" along normal blind 3.4
work_plane "WorkPlane89" AlongDistance 24 ExtraOffset 0
sketch "Outer lower sensor support clear of cam (1)" plane through (24, 0, 0) normal (1, 0, 0) x axis (0, 0, -1)
  line L1 (-4, 62) -> (-4, 49)
  line L2 (-35, 62) -> (-4, 62)
  line L3 (-35, 49) -> (-35, 62)
  line L4 (-4, 49) -> (-35, 49)
extrude "Extrude89" add sketch "Outer lower sensor support clear of cam (1)" along normal blind 10
work_plane "WorkPlane90" AlongDistance 24 ExtraOffset 0
sketch "Outer lower M3 insert (1)" plane through (24, 0, 0) normal (1, 0, 0) x axis (0, 0, -1)
  circle C1 centre (-19.85, 55) radius 2
extrude "Extrude90" cut sketch "Outer lower M3 insert (1)" along normal blind 6.8
work_plane "WorkPlane91" AlongDistance 30.7 ExtraOffset 0
sketch "Outer lower screw clearance (1)" plane through (30.7, 0, 0) normal (1, 0, 0) x axis (0, 0, -1)
  circle C1 centre (-19.85, 55) radius 1.7
extrude "Extrude91" cut sketch "Outer lower screw clearance (1)" along normal blind 3.4
work_plane "WorkPlane92" AlongDistance 23.9 ExtraOffset 0
sketch "Potentiometer body and lead clearance (1)" plane through (23.9, 0, 0) normal (1, 0, 0) x axis (0, 0, -1)
  line L1 (-8.5, 8) -> (-8.5, -8)
  line L2 (-31.2, 8) -> (-8.5, 8)
  line L3 (-31.2, -8) -> (-31.2, 8)
  line L4 (-8.5, -8) -> (-31.2, -8)
extrude "Extrude92" cut sketch "Potentiometer body and lead clearance (1)" along normal blind 10.2
work_plane "WorkPlane1" AlongDistance 34 ExtraOffset 0
sketch "Flat lower sensor panel" plane through (34, 0, 0) normal (1, 0, 0) x axis (0, 0, -1)
  line L1 (-4, 62) -> (-4, -62)
  line L2 (-34, 62) -> (-4, 62)
  line L3 (-34, -62) -> (-34, 62)
  line L4 (-4, -62) -> (-34, -62)
extrude "Extrude1" new body sketch "Flat lower sensor panel" along normal blind 3 bodies "G03R Lower removable potentiometer panel"
work_plane "WorkPlane2" AlongDistance 33.9 ExtraOffset 0
sketch "Sensor bushing clearance" plane through (33.9, 0, 0) normal (1, 0, 0) x axis (0, 0, -1)
  circle C1 centre (-19.85, 0) radius 3.6
extrude "Extrude2" cut sketch "Sensor bushing clearance" along normal blind 3.2
work_plane "WorkPlane3" AlongDistance 33.9 ExtraOffset 0
sketch "Radial mesh adjustment slot" plane through (33.9, 0, 0) normal (1, 0, 0) x axis (0, 0, -1)
  line L1 (-16.95, -53.3) -> (-16.95, -56.7)
  line L2 (-22.75, -53.3) -> (-16.95, -53.3)
  line L3 (-22.75, -56.7) -> (-22.75, -53.3)
  line L4 (-16.95, -56.7) -> (-22.75, -56.7)
extrude "Extrude3" cut sketch "Radial mesh adjustment slot" along normal blind 3.2
work_plane "WorkPlane1" AlongDistance 25 ExtraOffset 0
sketch "Lower panel M3x12 -55" plane through (25, 0, 0) normal (1, 0, 0) x axis (0, 0, -1)
  circle C1 centre (-19.85, -55) radius 1.5
extrude "Extrude1" new body sketch "Lower panel M3x12 -55" along normal blind 12 bodies "HARDWARE Lower panel M3x12 -55"
work_plane "WorkPlane2" AlongDistance 37 ExtraOffset 0
sketch "Button head" plane through (37, 0, 0) normal (1, 0, 0) x axis (0, 0, -1)
  circle C1 centre (-19.85, -55) radius 2.75
extrude "Extrude2" add sketch "Button head" along normal blind 3
work_plane "WorkPlane4" AlongDistance 33.9 ExtraOffset 0
sketch "Radial mesh adjustment slot (1)" plane through (33.9, 0, 0) normal (1, 0, 0) x axis (0, 0, -1)
  line L1 (-16.95, 56.7) -> (-16.95, 53.3)
  line L2 (-22.75, 56.7) -> (-16.95, 56.7)
  line L3 (-22.75, 53.3) -> (-22.75, 56.7)
  line L4 (-16.95, 53.3) -> (-22.75, 53.3)
extrude "Extrude4" cut sketch "Radial mesh adjustment slot (1)" along normal blind 3.2
work_plane "WorkPlane1" AlongDistance 25 ExtraOffset 0
sketch "Lower panel M3x12 55" plane through (25, 0, 0) normal (1, 0, 0) x axis (0, 0, -1)
  circle C1 centre (-19.85, 55) radius 1.5
extrude "Extrude1" new body sketch "Lower panel M3x12 55" along normal blind 12 bodies "HARDWARE Lower panel M3x12 55"
work_plane "WorkPlane2" AlongDistance 37 ExtraOffset 0
sketch "Button head" plane through (37, 0, 0) normal (1, 0, 0) x axis (0, 0, -1)
  circle C1 centre (-19.85, 55) radius 2.75
extrude "Extrude2" add sketch "Button head" along normal blind 3
position "Position3"
work_plane "WorkPlane74" AlongDistance -36 ExtraOffset 0
sketch "Top rail hanging suspension arm" plane through (-36, 0, 0) normal (1, 0, 0) x axis (0, 0, -1)
  line L1 (-33, -74.5) -> (-33, -55)
  line L2 (-102, -74.5) -> (-33, -74.5)
  line L3 (-102, -95) -> (-102, -74.5)
  line L4 (-111, -95) -> (-102, -95)
  line L5 (-111, -65) -> (-111, -95)
  line L6 (-57, -55) -> (-111, -65)
  line L7 (-33, -55) -> (-57, -55)
extrude "Extrude74" add sketch "Top rail hanging suspension arm" along normal blind 12
work_plane "WorkPlane75" AlongDistance 101.9 ExtraOffset 0
sketch "Top-access M5 mounting clearance" plane through (0, 0, 101.9) normal (0, 0, 1) x axis (1, 0, 0)
  circle C1 centre (-30, -85) radius 2.7
extrude "Extrude75" cut sketch "Top-access M5 mounting clearance" along normal blind 9.2
work_plane "WorkPlane1" AlongDistance 97 ExtraOffset 0
sketch "Top hanging rail M5x14 (-30, -1)" plane through (0, 0, 97) normal (0, 0, 1) x axis (1, 0, 0)
  circle C1 centre (-30, -85) radius 2.5
extrude "Extrude1" new body sketch "Top hanging rail M5x14 (-30, -1)" along normal blind 14 bodies "HARDWARE Top hanging rail M5x14 (-30, -1)"
work_plane "WorkPlane2" AlongDistance 111 ExtraOffset 0
sketch "Button head" plane through (0, 0, 111) normal (0, 0, 1) x axis (1, 0, 0)
  circle C1 centre (-30, -85) radius 4.25
extrude "Extrude2" add sketch "Button head" along normal blind 5
work_plane "WorkPlane76" AlongDistance -36 ExtraOffset 0
sketch "Top rail hanging suspension arm (1)" plane through (-36, 0, 0) normal (1, 0, 0) x axis (0, 0, -1)
  line L1 (-33, 74.5) -> (-33, 55)
  line L2 (-102, 74.5) -> (-33, 74.5)
  line L3 (-102, 95) -> (-102, 74.5)
  line L4 (-111, 95) -> (-102, 95)
  line L5 (-111, 65) -> (-111, 95)
  line L6 (-57, 55) -> (-111, 65)
  line L7 (-33, 55) -> (-57, 55)
extrude "Extrude76" add sketch "Top rail hanging suspension arm (1)" along normal blind 12
work_plane "WorkPlane77" AlongDistance 101.9 ExtraOffset 0
sketch "Top-access M5 mounting clearance (1)" plane through (0, 0, 101.9) normal (0, 0, 1) x axis (1, 0, 0)
  circle C1 centre (-30, 85) radius 2.7
extrude "Extrude77" cut sketch "Top-access M5 mounting clearance (1)" along normal blind 9.2
work_plane "WorkPlane1" AlongDistance 97 ExtraOffset 0
sketch "Top hanging rail M5x14 (-30, 1)" plane through (0, 0, 97) normal (0, 0, 1) x axis (1, 0, 0)
  circle C1 centre (-30, 85) radius 2.5
extrude "Extrude1" new body sketch "Top hanging rail M5x14 (-30, 1)" along normal blind 14 bodies "HARDWARE Top hanging rail M5x14 (-30, 1)"
work_plane "WorkPlane2" AlongDistance 111 ExtraOffset 0
sketch "Button head" plane through (0, 0, 111) normal (0, 0, 1) x axis (1, 0, 0)
  circle C1 centre (-30, 85) radius 4.25
extrude "Extrude2" add sketch "Button head" along normal blind 5
work_plane "WorkPlane93" AlongDistance 24 ExtraOffset 0
sketch "Top rail hanging suspension arm" plane through (24, 0, 0) normal (1, 0, 0) x axis (0, 0, -1)
  line L1 (-33, -74.5) -> (-33, -55)
  line L2 (-102, -74.5) -> (-33, -74.5)
  line L3 (-102, -95) -> (-102, -74.5)
  line L4 (-111, -95) -> (-102, -95)
  line L5 (-111, -65) -> (-111, -95)
  line L6 (-57, -55) -> (-111, -65)
  line L7 (-33, -55) -> (-57, -55)
extrude "Extrude93" add sketch "Top rail hanging suspension arm" along normal blind 12
work_plane "WorkPlane94" AlongDistance 101.9 ExtraOffset 0
sketch "Top-access M5 mounting clearance" plane through (0, 0, 101.9) normal (0, 0, 1) x axis (1, 0, 0)
  circle C1 centre (30, -85) radius 2.7
extrude "Extrude94" cut sketch "Top-access M5 mounting clearance" along normal blind 9.2
work_plane "WorkPlane1" AlongDistance 97 ExtraOffset 0
sketch "Top hanging rail M5x14 (30, -1)" plane through (0, 0, 97) normal (0, 0, 1) x axis (1, 0, 0)
  circle C1 centre (30, -85) radius 2.5
extrude "Extrude1" new body sketch "Top hanging rail M5x14 (30, -1)" along normal blind 14 bodies "HARDWARE Top hanging rail M5x14 (30, -1)"
work_plane "WorkPlane2" AlongDistance 111 ExtraOffset 0
sketch "Button head" plane through (0, 0, 111) normal (0, 0, 1) x axis (1, 0, 0)
  circle C1 centre (30, -85) radius 4.25
extrude "Extrude2" add sketch "Button head" along normal blind 5
work_plane "WorkPlane95" AlongDistance 24 ExtraOffset 0
sketch "Top rail hanging suspension arm (1)" plane through (24, 0, 0) normal (1, 0, 0) x axis (0, 0, -1)
  line L1 (-33, 74.5) -> (-33, 55)
  line L2 (-102, 74.5) -> (-33, 74.5)
  line L3 (-102, 95) -> (-102, 74.5)
  line L4 (-111, 95) -> (-102, 95)
  line L5 (-111, 65) -> (-111, 95)
  line L6 (-57, 55) -> (-111, 65)
  line L7 (-33, 55) -> (-57, 55)
extrude "Extrude95" add sketch "Top rail hanging suspension arm (1)" along normal blind 12
work_plane "WorkPlane96" AlongDistance 101.9 ExtraOffset 0
sketch "Top-access M5 mounting clearance (1)" plane through (0, 0, 101.9) normal (0, 0, 1) x axis (1, 0, 0)
  circle C1 centre (30, 85) radius 2.7
extrude "Extrude96" cut sketch "Top-access M5 mounting clearance (1)" along normal blind 9.2
work_plane "WorkPlane1" AlongDistance 97 ExtraOffset 0
sketch "Top hanging rail M5x14 (30, 1)" plane through (0, 0, 97) normal (0, 0, 1) x axis (1, 0, 0)
  circle C1 centre (30, 85) radius 2.5
extrude "Extrude1" new body sketch "Top hanging rail M5x14 (30, 1)" along normal blind 14 bodies "HARDWARE Top hanging rail M5x14 (30, 1)"
work_plane "WorkPlane2" AlongDistance 111 ExtraOffset 0
sketch "Button head" plane through (0, 0, 111) normal (0, 0, 1) x axis (1, 0, 0)
  circle C1 centre (30, 85) radius 4.25
extrude "Extrude2" add sketch "Button head" along normal blind 5
work_plane "WorkPlane97" AlongDistance 34 ExtraOffset 0
sketch "Recess seat for removable lower sensor panel" plane through (34, 0, 0) normal (1, 0, 0) x axis (0, 0, -1)
  line L1 (-3.8, 62.2) -> (-3.8, -62.2)
  line L2 (-34.2, 62.2) -> (-3.8, 62.2)
  line L3 (-34.2, -62.2) -> (-34.2, 62.2)
  line L4 (-3.8, -62.2) -> (-34.2, -62.2)
extrude "Extrude97" cut sketch "Recess seat for removable lower sensor panel" along normal blind 2.1
position "Position4"
work_plane "WorkPlane1" AlongDistance -320 ExtraOffset 0
sketch "Panel resting on frame top" plane through (-320, 0, 0) normal (1, 0, 0) x axis (0, 0, -1)
  line L1 (-55, 95) -> (-55, -95)
  line L2 (-58, 95) -> (-55, 95)
  line L3 (-58, -95) -> (-58, 95)
  line L4 (-55, -95) -> (-58, -95)
extrude "Extrude1" new body sketch "Panel resting on frame top" along normal blind 640
work_plane "WorkPlane2" AlongDistance -10 ExtraOffset 0
sketch "20 by 136 mm lever sweep opening" plane through (-10, 0, 0) normal (1, 0, 0) x axis (0, 0, -1)
  line L1 (-54.9, 68) -> (-54.9, -68)
  line L2 (-58.1, 68) -> (-54.9, 68)
  line L3 (-58.1, -68) -> (-58.1, 68)
  line L4 (-54.9, -68) -> (-58.1, -68)
extrude "Extrude2" cut sketch "20 by 136 mm lever sweep opening" along normal blind 20
work_plane "WorkPlane3" AlongDistance -36.5 ExtraOffset 0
